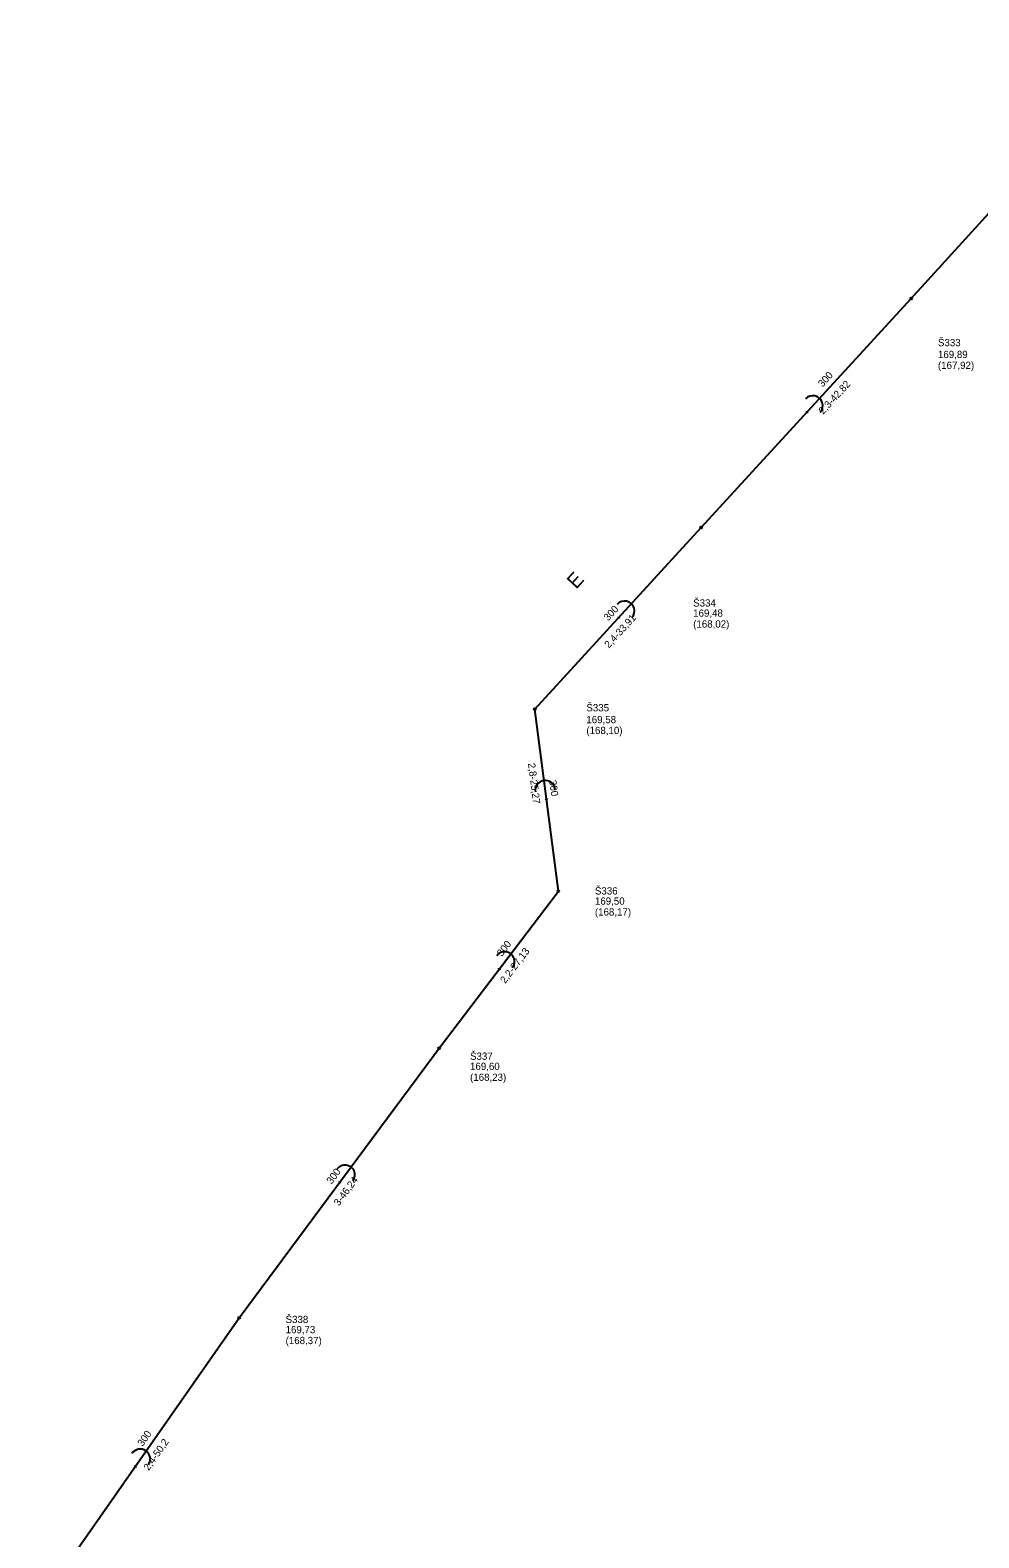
# Model space of a CAD drawing. Extents: x -548529 to -543591, y -1201432 to -1192608.
# Drawn here: x -548240.7 to -548110, y -1196187.8 to -1195980.2 of the extents above; entities that cross this region are included whole.
import ezdxf

# ---------------------------------------------------------------- set-up
doc = ezdxf.new("R2010")
doc.units = 0
for name, color, linetype in [('C3D_Bod-Značky', 7, 'Continuous'), ('C3D_Křižovatka', 7, 'Continuous'), ('C3D_Netisknutelná', 7, 'Continuous'), ('C3D_PP-zobrazeni v PR', 7, 'Continuous'), ('C3D_PR-Popisek', 7, 'Continuous'), ('C3D_SPR-Popisek', 7, 'Continuous'), ('C3D_Tlakove_potrubi_Popis', 7, 'Continuous'), ('C3D_ZPR-Formaty', 7, 'Continuous')]:
    doc.layers.add(name, color=color, linetype=linetype)

# ---------------------------------------------------------------- blocks, each defined once
blk = doc.blocks.new('100')
at = {"layer": 'Defpoints'}
blk.add_circle((0, 0), 0.127, dxfattribs=at)
blk = doc.blocks.new('91')
at = {"layer": 'Defpoints'}
blk.add_lwpolyline([(0.08, 0.14), (0.19, 0), (0.08, -0.14)], dxfattribs=at)
blk.add_arc((1.37, 0), 1.37, 270, 90, dxfattribs=at)

msp = doc.modelspace()

# ---------------------------------------------------------------- linework, layer by layer
at = {"layer": 'C3D_Bod-Značky'}
for points in [[(-548119.35, -1196017.17), (-548085.74, -1195980.22)], [(-548148.31, -1196048.71), (-548119.35, -1196017.17)], [(-548171.2, -1196073.73), (-548148.31, -1196048.71)], [(-548167.96, -1196098.8), (-548171.2, -1196073.73)], [(-548184.38, -1196120.4), (-548167.96, -1196098.8)], [(-548211.91, -1196157.55), (-548184.38, -1196120.4)], [(-548240.7, -1196198.68), (-548211.91, -1196157.55)]]:
    msp.add_lwpolyline(points, dxfattribs=at)

# ---------------------------------------------------------------- block references
at = {"layer": 'C3D_PP-zobrazeni v PR'}
for p, xscale, yscale, rotation in [((-548119.35, -1196017.17), 1.0000000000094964, 1.0000000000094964, -132.0000013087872), ((-548148.31, -1196048.71), 1.0000000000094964, 1.0000000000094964, 47.99999869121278), ((-548171.2, -1196073.73), 0.9999999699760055, 0.9999999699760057, 73.00000033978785), ((-548167.96, -1196098.8), 1.0000000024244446, 1.0000000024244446, -104.00000032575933), ((-548184.38, -1196120.4), 1.000000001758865, 1.000000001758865, -125.99999933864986), ((-548211.91, -1196157.55), 1.000000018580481, 1.000000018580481, -125.00000023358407)]:
    msp.add_blockref('100', p, dxfattribs=dict(at, xscale=xscale, yscale=yscale, rotation=rotation))
at = {"layer": 'C3D_SPR-Popisek'}
for p, xscale, yscale, rotation in [((-548133.83, -1196032.94), 1.0000000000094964, 1.0000000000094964, 47.99999869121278), ((-548159.755, -1196061.22), 1.0000000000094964, 1.0000000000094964, 47.99999869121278), ((-548169.58, -1196086.265), 0.9999999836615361, 0.9999999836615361, 98.00000038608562), ((-548176.17, -1196109.6), 0.9999999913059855, 0.9999999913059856, 52.999998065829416), ((-548198.145, -1196138.975), 1.000000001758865, 1.000000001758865, 54.00000066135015), ((-548226.305, -1196178.115), 0.9999999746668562, 0.999999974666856, 55.999999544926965)]:
    msp.add_blockref('91', p, dxfattribs=dict(at, xscale=xscale, yscale=yscale, rotation=rotation))

# ---------------------------------------------------------------- texts
at = {"layer": 'C3D_Křižovatka'}
for s, p in [('Š333', (-548115.68, -1196023.74)), ('Š334', (-548149.39, -1196059.59)), ('Š335', (-548164.1, -1196074.02)), ('Š336', (-548162.92, -1196099.24)), ('Š337', (-548180.12, -1196122)), ('Š338', (-548205.52, -1196158.25))]:
    msp.add_text(s, height=1, dxfattribs=at).set_placement(p)
at = {"layer": 'C3D_Netisknutelná'}
msp.add_text('E', height=2, rotation=47.55, dxfattribs=at).set_placement((-548165.507, -1196057.278))
at = {"layer": 'C3D_PR-Popisek'}
for rotation, p in [(47.44, (-548131.57, -1196029.441)), (47.55, (-548161.094, -1196061.642)), (277.36, (-548169.222, -1196083.548)), (52.76, (-548175.715, -1196107.845)), (53.46, (-548199.189, -1196139.209)), (55.01, (-548225.203, -1196175.316))]:
    msp.add_text('300', height=1, rotation=rotation, dxfattribs=at).set_placement(p)
at = {"layer": 'C3D_Tlakove_potrubi_Popis'}
for s, p in [('(167,92)', (-548115.68, -1196026.87)), ('169,89 ', (-548115.68, -1196025.37)), ('(168,02)', (-548149.39, -1196062.49)), ('169,48 ', (-548149.39, -1196060.99)), ('(168,10)', (-548164.1, -1196077.15)), ('169,58 ', (-548164.1, -1196075.65)), ('(168,17)', (-548162.92, -1196102.14)), ('169,50 ', (-548162.92, -1196100.64)), ('(168,23)', (-548180.12, -1196124.9)), ('169,60 ', (-548180.12, -1196123.4)), ('169,73 ', (-548205.52, -1196159.65)), ('(168,37)', (-548205.52, -1196161.15))]:
    msp.add_text(s, height=1, dxfattribs=at).set_placement(p)
at = {"layer": 'C3D_ZPR-Formaty'}
for s, rotation, p in [('2,3-42,82', 47.44, (-548131.475, -1196033.187)), ('2,4-33,91', 47.55, (-548160.993, -1196065.389)), ('2,8-25,27', 277.36, (-548172.146, -1196081.199)), ('2,2-27,13', 52.76, (-548175.275, -1196111.561)), ('3-46,24', 53.46, (-548198.176, -1196142.208)), ('2,4-50,2', 55.01, (-548224.366, -1196178.652))]:
    msp.add_text(s, height=1, rotation=rotation, dxfattribs=at).set_placement(p)

doc.saveas('drawing.dxf')
